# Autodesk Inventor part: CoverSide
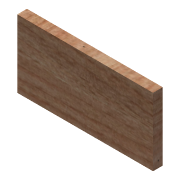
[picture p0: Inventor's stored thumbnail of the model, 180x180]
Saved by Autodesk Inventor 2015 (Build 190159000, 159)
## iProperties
Created: 2016-02
Part Number: CoverSide
Material: Wood (Birch)
Document SubType Name: Modeling
Designer: Hafliði
Density: 0.55 g/cm^3
Appearance: Birch - Natural Polished
Mass: 53.9 g
Surface Area: 238 cm^2
Volume: 98 cm^3
Author: Hafliði
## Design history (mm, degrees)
sketch "Sketch1"
  geometry: L1 (-70, 35)-(70, 35); L2 (70, 35)-(70, -35); L3 (70, -35)-(-70, -35); L4 (-70, -35)-(-70, 35); L5 (-70, 35)-(70, -35); L6 (70, 35)-(-70, -35); 1 further point
  constraints: 12 end point, 2 midpoint, 2 parallel, 1 horizontal, 1 perpendicular
  dimensions: "d0" = 140 distance of L2.end L3.end; "d1" = 70 distance of L1.end L2.end
extrude "Extrusion1" new body sketch "Sketch1" distance "d2" = 10; taper "d3" = 0 deg
body "Solid1"
